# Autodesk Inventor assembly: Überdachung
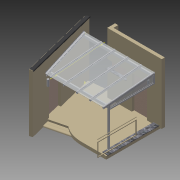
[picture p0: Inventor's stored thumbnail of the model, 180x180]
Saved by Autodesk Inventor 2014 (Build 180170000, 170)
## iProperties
Created: 2013-09
Part Number: Überdachung
Document SubType Name: Assembly
Designer: Stefan Tammegger
Author: Stefan Tammegger
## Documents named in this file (24)
- Q:\PROJEKTE\INVENTOR\Scharinger Christian\Überdachung.iam
- Q:\PROJEKTE\INVENTOR\Scharinger Christian\Bestand.ipt
- Q:\PROJEKTE\INVENTOR\Scharinger Christian\Auflager Wand.ipt
- Q:\PROJEKTE\INVENTOR\Scharinger Christian\Auflager Traufe.ipt
- Q:\PROJEKTE\INVENTOR\Scharinger Christian\Säule freistehend.ipt
- Q:\PROJEKTE\INVENTOR\Scharinger Christian\Konsole Büro.ipt
- Q:\PROJEKTE\INVENTOR\Scharinger Christian\Konsole Wand.ipt
- Q:\PROJEKTE\INVENTOR\Scharinger Christian\Sparren.ipt
- Q:\PROJEKTE\INVENTOR\Scharinger Christian\Sparren schräg.ipt
- Q:\PROJEKTE\INVENTOR\Scharinger Christian\Überleger Schiebeverglasung.ipt
- Q:\PROJEKTE\INVENTOR\Scharinger Christian\Glasrahmen über Schiebefeld.ipt
- Q:\PROJEKTE\INVENTOR\Scharinger Christian\Glas Seitenteil.ipt
- Q:\PROJEKTE\INVENTOR\Scharinger Christian\Glasklemmleisten.ipt
- Q:\PROJEKTE\INVENTOR\Scharinger Christian\Klemmleiste Büro.ipt
- Q:\PROJEKTE\INVENTOR\Scharinger Christian\Glas Dach.ipt
- Q:\PROJEKTE\INVENTOR\Scharinger Christian\Glas Dach schräg.ipt
- Q:\PROJEKTE\INVENTOR\Scharinger Christian\Abtropfblech Büro.ipt
- C:\Program Files (x86)\Autodesk\Content Service\de-DE\DIN 1587\DIN 1587 - M12 x 1,75.ipt
- C:\Program Files (x86)\Autodesk\Content Service\de-DE\DIN EN 24 017\ISO 4017 - M12 x 25DIN EN.ipt
- C:\Program Files (x86)\Autodesk\Content Service\de-DE\DIN EN 24 017\ISO 4017 - M12 x 100DIN EN.ipt
- C:\Program Files (x86)\Autodesk\Content Service\de-DE\ISO 4032(1)\ISO 4032 - M12DIN EN.ipt
- C:\Program Files (x86)\Autodesk\Content Service\de-DE\ISO 10642(2)\ISO 10642  - M10  x  45.ipt
- C:\Program Files (x86)\Autodesk\Content Service\de-DE\ISO 7045(1)\ISO 7045 - M5 x 45 - 4.8 - HDIN EN ISO.ipt
- C:\Program Files (x86)\Autodesk\Content Service\de-DE\DIN EN 24 017\ISO 4017 - M12 x 40DIN EN.ipt
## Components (124 placed, 23 different names)
1. Bestand:1 — Fluchtend:1, Fluchtend:2, Fluchtend:3, Fluchtend:4, Fluchtend:5, Fluchtend:6, Fluchtend:7, Fluchtend:9, Fluchtend:11, Fluchtend:12, Fluchtend:13, Fluchtend:14, Fluchtend:17
2. Auflager Wand:1 — Fluchtend:1, Fluchtend:4, Fluchtend:8, Fluchtend:13, Fluchtend:15, Passend:2, Passend:4, Fluchtend:22
3. Auflager Traufe:1 — Fluchtend:2, Fluchtend:3, Fluchtend:8, Fluchtend:9, Fluchtend:16, Passend:1, Passend:3, Passend:7
4. Säule freistehend:1 — Fluchtend:5, Fluchtend:6, Fluchtend:7, Fluchtend:19, Fluchtend:20, Fluchtend:21
5. Konsole Büro:1 — Fluchtend:11, Fluchtend:12
6. Sparren schräg:1 — Fluchtend:17, Passend:3, Passend:4, Passend:5, Passend:7, Fluchtend:18, Fluchtend:31, Fluchtend:32, Fluchtend:35, Fluchtend:38
7. Überleger Schiebeverglasung:1 — Fluchtend:19, Fluchtend:20, Fluchtend:21, Fluchtend:22, Fluchtend:23, Fluchtend:24, Fluchtend:25
8. Glasrahmen über Schiebefeld:1 — Fluchtend:23, Fluchtend:24, Fluchtend:25, Fluchtend:26, Fluchtend:27, Fluchtend:28
9. Glas Seitenteil:1 — Fluchtend:27, Fluchtend:28
10. Klemmleiste Büro:1 — Fluchtend:31, Fluchtend:32, Fluchtend:37
11. Glas Dach schräg:1 — Fluchtend:35, Fluchtend:36
12. Abtropfblech Büro:1 — Fluchtend:37, Fluchtend:38
13. DIN EN 24017 M12 x 40:1
14. DIN EN 24017 M12 x 40:2
15. DIN 1587 M12:1
16. DIN 1587 M12:2
17. DIN 1587 M12:3
18. DIN 1587 M12:4
19. DIN 1587 M12:5
20. DIN 1587 M12:6
21. DIN 1587 M12:7
22. DIN 1587 M12:8
23. DIN 1587 M12:9
24. DIN 1587 M12:10
25. DIN 1587 M12:11
26. DIN 1587 M12:12
27. DIN EN 24017 M12 x 25:1
28. DIN EN 24017 M12 x 25:2
29. DIN EN 24017 M12 x 25:3
30. DIN EN 24017 M12 x 25:4
31. DIN EN 24017 M12 x 25:5
32. DIN EN 24017 M12 x 25:6
33. DIN EN 24017 M12 x 25:7
34. DIN EN 24017 M12 x 25:8
35. DIN EN 24017 M12 x 25:9
36. DIN EN 24017 M12 x 25:10
37. DIN EN 24017 M12 x 100:1
38. DIN EN 24017 M12 x 100:2
39. DIN EN 24017 M12 x 100:3
40. DIN EN 24017 M12 x 100:4
41. DIN EN 24017 M12 x 100:5
42. DIN EN 24017 M12 x 100:6
43. DIN EN 24032 M12:1
44. DIN EN 24032 M12:2
45. DIN EN 24032 M12:3
46. DIN EN 24032 M12:4
47. DIN EN 24032 M12:5
48. DIN EN 24032 M12:6
49. DIN EN 24032 M12:7
50. DIN EN 24032 M12:8
51. DIN EN 24032 M12:9
52. DIN EN 24032 M12:10
53. DIN EN 24017 M12 x 100:7
54. DIN EN 24017 M12 x 100:8
55. DIN EN 24017 M12 x 100:9
56. DIN EN 24017 M12 x 100:10
57. DIN EN 24017 M12 x 100:11
58. DIN EN 24017 M12 x 100:12
59. DIN EN ISO 10642 M10  x  45:1
60. DIN EN ISO 10642 M10  x  45:2
61. DIN EN ISO 7045 H M5 x 45 - 4.8 - H:1
62. DIN EN ISO 7045 H M5 x 45 - 4.8 - H:2
63. DIN EN ISO 7045 H M5 x 45 - 4.8 - H:3
64. DIN EN ISO 7045 H M5 x 45 - 4.8 - H:4
65. DIN EN ISO 7045 H M5 x 45 - 4.8 - H:5
66. DIN EN ISO 7045 H M5 x 45 - 4.8 - H:6
67. DIN EN ISO 7045 H M5 x 45 - 4.8 - H:7
68. DIN EN ISO 7045 H M5 x 45 - 4.8 - H:8
69. DIN EN ISO 7045 H M5 x 45 - 4.8 - H:9
70. DIN EN ISO 7045 H M5 x 45 - 4.8 - H:10
71. DIN EN ISO 7045 H M5 x 45 - 4.8 - H:11
72. DIN EN ISO 7045 H M5 x 45 - 4.8 - H:12
73. DIN EN ISO 7045 H M5 x 45 - 4.8 - H:13
74. DIN EN ISO 7045 H M5 x 45 - 4.8 - H:14
75. DIN EN ISO 7045 H M5 x 45 - 4.8 - H:15
76. DIN EN ISO 7045 H M5 x 45 - 4.8 - H:16
77. DIN EN ISO 7045 H M5 x 45 - 4.8 - H:17
78. DIN EN ISO 7045 H M5 x 45 - 4.8 - H:18
79. DIN EN ISO 7045 H M5 x 45 - 4.8 - H:19
80. DIN EN ISO 7045 H M5 x 45 - 4.8 - H:20
81. DIN EN ISO 7045 H M5 x 45 - 4.8 - H:21
82. DIN EN ISO 7045 H M5 x 45 - 4.8 - H:22
83. DIN EN ISO 7045 H M5 x 45 - 4.8 - H:23
84. DIN EN ISO 7045 H M5 x 45 - 4.8 - H:24
85. DIN EN ISO 7045 H M5 x 45 - 4.8 - H:25
86. DIN EN ISO 7045 H M5 x 45 - 4.8 - H:26
87. DIN EN ISO 7045 H M5 x 45 - 4.8 - H:27
88. DIN EN ISO 7045 H M5 x 45 - 4.8 - H:28
89. DIN EN ISO 7045 H M5 x 45 - 4.8 - H:29
90. DIN EN ISO 7045 H M5 x 45 - 4.8 - H:30
91. DIN EN ISO 7045 H M5 x 45 - 4.8 - H:31
92. DIN EN ISO 7045 H M5 x 45 - 4.8 - H:32
93. DIN EN ISO 7045 H M5 x 45 - 4.8 - H:33
94. DIN EN ISO 7045 H M5 x 45 - 4.8 - H:34
95. DIN EN ISO 7045 H M5 x 45 - 4.8 - H:35
96. DIN EN ISO 7045 H M5 x 45 - 4.8 - H:36
97. DIN EN ISO 7045 H M5 x 45 - 4.8 - H:37
98. DIN EN ISO 7045 H M5 x 45 - 4.8 - H:38
99. DIN EN ISO 7045 H M5 x 45 - 4.8 - H:39
100. DIN EN ISO 7045 H M5 x 45 - 4.8 - H:40
101. DIN EN ISO 7045 H M5 x 45 - 4.8 - H:41
102. DIN EN ISO 7045 H M5 x 45 - 4.8 - H:42
103. DIN EN ISO 7045 H M5 x 45 - 4.8 - H:43
104. DIN EN ISO 7045 H M5 x 45 - 4.8 - H:44
105. DIN EN ISO 7045 H M5 x 45 - 4.8 - H:45
106. DIN EN ISO 7045 H M5 x 45 - 4.8 - H:46
107. DIN EN ISO 7045 H M5 x 45 - 4.8 - H:47
108. DIN EN ISO 7045 H M5 x 45 - 4.8 - H:48
109. Konsole Wand:1 — Fluchtend:14, Fluchtend:15
110. Konsole Wand:2
111. Sparren:1 — Fluchtend:16, Passend:1, Passend:2, Fluchtend:26, Fluchtend:29, Fluchtend:30, Fluchtend:33, Fluchtend:34
112. Sparren:2
113. Sparren:3
114. Sparren:4
115. Sparren:5 — Passend:5, Fluchtend:18
116. Glasklemmleisten:1 — Fluchtend:29, Fluchtend:30
117. Glasklemmleisten:2
118. Glasklemmleisten:3
119. Glasklemmleisten:4
120. Glasklemmleisten:5 — Fluchtend:36
121. Glas Dach:1 — Fluchtend:33, Fluchtend:34
122. Glas Dach:2
123. Glas Dach:3
124. Glas Dach:4
## Component patterns: Wandkonsolen (2 elements), Sparren (5 elements), Klemmleisten (5 elements), Glas Dach (4 elements)
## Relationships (43: Flush 37, Mate 6)
- Fluchtend:1 [Flush]: Bestand:1 ↔ Auflager Wand:1
- Fluchtend:2 [Flush]: Bestand:1 ↔ Auflager Traufe:1
- Fluchtend:3 [Flush]: Bestand:1 ↔ Auflager Traufe:1
- Fluchtend:4 [Flush]: Bestand:1 ↔ Auflager Wand:1
- Fluchtend:5 [Flush]: Bestand:1 ↔ Säule freistehend:1
- Fluchtend:6 [Flush]: Bestand:1 ↔ Säule freistehend:1
- Fluchtend:7 [Flush]: Bestand:1 ↔ Säule freistehend:1
- Fluchtend:8 [Flush]: Auflager Wand:1 ↔ Auflager Traufe:1
- Fluchtend:9 [Flush]: Bestand:1 ↔ Auflager Traufe:1
- Fluchtend:11 [Flush]: Bestand:1 ↔ Konsole Büro:1
- Fluchtend:12 [Flush]: Bestand:1 ↔ Konsole Büro:1
- Fluchtend:13 [Flush]: Bestand:1 ↔ Auflager Wand:1
- Fluchtend:14 [Flush]: Bestand:1 ↔ Konsole Wand:1
- Fluchtend:15 [Flush]: Auflager Wand:1 ↔ Konsole Wand:1
- Fluchtend:16 [Flush]: Auflager Traufe:1 ↔ Sparren:1
- Passend:1 [Mate]: Auflager Traufe:1 ↔ Sparren:1
- Passend:2 [Mate]: Auflager Wand:1 ↔ Sparren:1
- Fluchtend:17 [Flush]: Bestand:1 ↔ Sparren schräg:1
- Passend:3 [Mate]: Auflager Traufe:1 ↔ Sparren schräg:1
- Passend:4 [Mate]: Auflager Wand:1 ↔ Sparren schräg:1
- Passend:5 [Mate]: Sparren schräg:1 ↔ Sparren:5
- Passend:7 [Mate]: Auflager Traufe:1 ↔ Sparren schräg:1
- Fluchtend:18 [Flush]: Sparren schräg:1 ↔ Sparren:5
- Fluchtend:19 [Flush]: Säule freistehend:1 ↔ Überleger Schiebeverglasung:1
- Fluchtend:20 [Flush]: Säule freistehend:1 ↔ Überleger Schiebeverglasung:1
- Fluchtend:21 [Flush]: Säule freistehend:1 ↔ Überleger Schiebeverglasung:1
- Fluchtend:22 [Flush]: Auflager Wand:1 ↔ Überleger Schiebeverglasung:1
- Fluchtend:23 [Flush]: Überleger Schiebeverglasung:1 ↔ Glasrahmen über Schiebefeld:1
- Fluchtend:24 [Flush]: Überleger Schiebeverglasung:1 ↔ Glasrahmen über Schiebefeld:1
- Fluchtend:25 [Flush]: Überleger Schiebeverglasung:1 ↔ Glasrahmen über Schiebefeld:1
- Fluchtend:26 [Flush]: Glasrahmen über Schiebefeld:1 ↔ Sparren:1
- Fluchtend:27 [Flush]: Glasrahmen über Schiebefeld:1 ↔ Glas Seitenteil:1
- Fluchtend:28 [Flush]: Glasrahmen über Schiebefeld:1 ↔ Glas Seitenteil:1
- Fluchtend:29 [Flush]: Sparren:1 ↔ Glasklemmleisten:1
- Fluchtend:30 [Flush]: Sparren:1 ↔ Glasklemmleisten:1
- Fluchtend:31 [Flush]: Sparren schräg:1 ↔ Klemmleiste Büro:1
- Fluchtend:32 [Flush]: Sparren schräg:1 ↔ Klemmleiste Büro:1
- Fluchtend:33 [Flush]: Sparren:1 ↔ Glas Dach:1
- Fluchtend:34 [Flush]: Sparren:1 ↔ Glas Dach:1
- Fluchtend:35 [Flush]: Sparren schräg:1 ↔ Glas Dach schräg:1
- Fluchtend:36 [Flush]: Glas Dach schräg:1 ↔ Glasklemmleisten:5
- Fluchtend:37 [Flush]: Klemmleiste Büro:1 ↔ Abtropfblech Büro:1
- Fluchtend:38 [Flush]: Sparren schräg:1 ↔ Abtropfblech Büro:1
